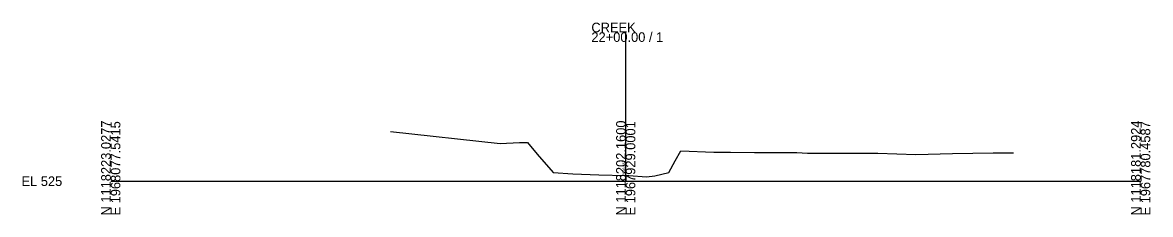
# Model space of a CAD drawing. Extents: x 9974 to 10303, y 9990 to 19550.
# Drawn here: x 9974.3 to 10302.8, y 11490.3 to 11546.2 of the extents above; entities that cross this region are included whole.
import ezdxf

# ---------------------------------------------------------------- set-up
doc = ezdxf.new("R2010")
doc.units = 0
for name, color, linetype in [('Level 10', 7, 'Continuous'), ('Level 60', 7, 'Continuous'), ('Level 63', 7, 'Continuous')]:
    doc.layers.add(name, color=color, linetype=linetype)

msp = doc.modelspace()

# ---------------------------------------------------------------- linework, layer by layer
at = {"layer": 'Level 60'}
for p, q in [((10081.46, 11514.47), (10113.45, 11510.95)), ((10113.45, 11510.95), (10119.09, 11511.25)), ((10119.09, 11511.25), (10121.41, 11511.27)), ((10121.41, 11511.27), (10124.25, 11507.9)), ((10164.41, 11505.93), (10166.06, 11508.87)), ((10166.06, 11508.87), (10175.71, 11508.48)), ((10124.25, 11507.9), (10128.83, 11502.56)), ((10162.56, 11502.58), (10164.41, 11505.93)), ((10175.71, 11508.48), (10180.5, 11508.43)), ((10180.5, 11508.43), (10187.51, 11508.32)), ((10187.51, 11508.32), (10199.81, 11508.41)), ((10199.81, 11508.41), (10202.91, 11508.19)), ((10202.91, 11508.19), (10223.41, 11508.16)), ((10223.41, 11508.16), (10234.48, 11507.75)), ((10234.48, 11507.75), (10245.17, 11508.03)), ((10245.17, 11508.03), (10257.07, 11508.25)), ((10257.07, 11508.25), (10262.98, 11508.3)), ((10128.83, 11502.56), (10134.64, 11502.18)), ((10134.64, 11502.18), (10142.19, 11501.87)), ((10158.47, 11501.53), (10162.56, 11502.58)), ((10142.19, 11501.87), (10150, 11501.66)), ((10150, 11501.66), (10150.94, 11501.63)), ((10150.94, 11501.63), (10156.08, 11501.3)), ((10156.08, 11501.3), (10158.47, 11501.53))]:
    msp.add_line(p, q, dxfattribs=at)
at = {"layer": 'Level 63'}
for p, q in [((10150, 11500), (10150, 11543.4)), ((10000, 11500), (10150, 11500)), ((10150, 11500), (10300, 11500))]:
    msp.add_line(p, q, dxfattribs=at)

# ---------------------------------------------------------------- texts
at = {"layer": 'Level 10'}
msp.add_text('526.657', height=0.8, rotation=90, dxfattribs=at).set_placement((10149.9, 11502.16))
at = {"layer": 'Level 63'}
for s, p in [('CREEK', (10140, 11543.4)), ('22+00.00 / 1', (10140, 11540.6)), ('EL 525', (9974, 11498.6))]:
    msp.add_text(s, height=2.8, dxfattribs=at).set_placement(p)
for s, p in [('N 1118223.0277', (10000, 11490)), ('E 1968077.5415', (10002.8, 11490)), ('N 1118202.1600', (10150, 11490)), ('E 1967929.0001', (10152.8, 11490)), ('N 1118181.2924', (10300, 11490)), ('E 1967780.4587', (10302.8, 11490))]:
    msp.add_text(s, height=2.8, rotation=90, dxfattribs=at).set_placement(p)

doc.saveas('drawing.dxf')
